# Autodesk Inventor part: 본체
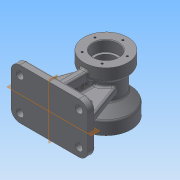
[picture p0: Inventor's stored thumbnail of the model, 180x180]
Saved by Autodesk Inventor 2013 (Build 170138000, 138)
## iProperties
Created: 2015-08
Part Number: 본체
Material: 일반
Document SubType Name: Modeling
Designer: WINDOWS7
Density: 1 g/cm^3
Author: WINDOWS7
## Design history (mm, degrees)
sketch "스케치1"
  geometry: 1 further point
sketch "스케치2"
  geometry: C1 r 26 at (0, 90); 1 further point
  constraints: 1 centre point, 1 vertical alignment
  dimensions: "d0" = 52 diameter of C1; "d2" = 90 distance of C1.centre point (0, 0)
extrude "돌출1" new body sketch "스케치2" distance "d3" = 90; taper "d4" = 0 deg
sketch "스케치3"
  geometry: C1 r 26 at (0, 0) reference; C2 r 35 at (0, 0); 1 further point
  constraints: 1 centre point, 1 coincident
  dimensions: "d5" = 70 diameter of C2
extrude "돌출2" join sketch "스케치3" distance "d7" = 20; taper "d8" = 0 deg
sketch "스케치4"
  geometry: C1 r 26 at (0, 0) reference; C2 r 40 at (0, 0); 1 further point
  constraints: 1 centre point, 1 coincident
  dimensions: "d9" = 80 diameter of C2
extrude "돌출3" join sketch "스케치4" distance "d11" = 20; taper "d12" = 0 deg
sketch "스케치5"
  geometry: L1 (125, 0)-(125, -20) reference; L2 (116, -20)-(116, -70) reference; L3 (130, -90)-(130, -70) reference; L4 (55, 0)-(55, -20) reference; L5 (64, -20)-(64, -70) reference; L6 (55, 0)-(125, 0) reference; L7 (64, -20)-(116, -20) reference; L8 (116, -70)-(64, -70) reference; L9 (130, -90)-(50, -90) reference; L10 (90, 0)-(90, -90); L11 (125, -20)-(116, -25.196); L12 (130, -70)-(116, -53.315); L13 (116, -25.196)-(116, -20); L14 (116, -53.315)-(116, -70); 1 further point
  constraints: 10 end point, 2 midpoint, 2 point on line, 1 collinear, 1 parallel
  dimensions: "d13" = 60 deg angle of L2 L11; "d14" = 40 deg angle of L2 L12
revolve "회전1" sketch "스케치5" stored, may be unused: angle "d15" = 90 deg
sketch "스케치6"
  geometry: L1 (61, 0.744)-(-61, 0.744); L2 (-61, 0.744)-(-61, -79.256); L3 (-61, -79.256)-(61, -79.256); L4 (61, -79.256)-(61, 0.744); L5 (26, -25.196)-(26, -53.315) reference; L6 (-26, -25.196)-(-26, -53.315) reference; L7 (-35, 0)-(35, 0) reference; 4 further points
  constraints: 8 end point, 3 midpoint, 2 parallel, 1 horizontal, 1 horizontal alignment, 1 perpendicular, 1 vertical alignment
  dimensions: "d16" = 80 distance of L3.end L1.start; "d18" = 122 distance of L2.end L3.end
extrude "돌출4" join sketch "스케치6" distance "d19" = 12; taper "d20" = 0 deg
node "작업 평면1"
sketch "스케치7"
  geometry: L1 (122, 0)-(0, 0) reference; L2 (0, 0)-(0, 12) reference; L3 (122, 12)-(0, 12) reference; L4 (122, 0)-(122, 12) reference; L5 (10, 12)-(37.488, 87.523); L6 (37.488, 87.523)-(84.512, 87.523); L7 (84.512, 87.523)-(112, 12); 1 further point
  constraints: 6 end point, 2 point on line, 1 perpendicular
  dimensions: "d22" = 10 distance of L3.start L7.end; "d23" = 70 deg angle of L3 L7; "d24" = 10 distance of L2.end L5.start; "d25" = 70 deg angle of L3 L5; "d26" = 47.02406 distance of L5.end L6.end
extrude "돌출5" join sketch "스케치7" stored distance "d27" = 12; taper "d28" = 0 deg
node "작업 평면2"
sketch "스케치8"
  geometry: L1 (80, 12)-(0, 12) reference; L2 (80, 0)-(0, 0) reference; L3 (0, 0)-(0, 12) reference; L4 (80, 12)-(0, 12) reference; L5 (80, 0)-(80, 12) reference; L6 (10, 83.257)-(10, 12); L7 (10, 83.257)-(82.565, 83.257); L8 (82.565, 83.257)-(70, 12); 1 further point
  constraints: 6 end point, 2 perpendicular, 2 point on line, 1 parallel
  dimensions: "d30" = 10 distance of L8.end L1.start; "d31" = 80 deg angle of L1 L8; "d32" = 10 distance of L1.end L6.end; "d33" = 72.5645 distance of L6.start L7.end
extrude "돌출6" join sketch "스케치8" stored distance "d34" = 12; taper "d35" = 0 deg
sketch "스케치9"
  geometry: L1 (79, 42)-(91, 42); L2 (91, 42)-(91, 24); L3 (91, 24)-(79, 24); L4 (79, 24)-(79, 42); A1 r 6 centre (85, 36) between (91, 36) and (79, 36); A2 r 6 centre (85, 30) between (79, 30) and (91, 30); 1 further point
  constraints: 8 end point, 5 point on circle, 4 point on line, 2 centre point, 2 parallel, 2 tangent, 1 equal radius, 1 horizontal, 1 perpendicular, 1 vertical alignment
  dimensions: "d36" = 12 distance of L1.start L1.end; "d38" = 18 distance of L3.end L1.start; "d39" = 12 diameter of A1; "d40" = 24 horizontal distance of point (61, 0) A2.centre; "d41" = 30 vertical distance of point (61, 0) A2.centre
extrude "돌출7" cut sketch "스케치9" distance "d42" = 12; taper "d43" = 0 deg
sketch "스케치10"
  geometry: C1 r 20 at (0, 90); A1 r 35 centre (0, 90) between (0, 125) and (35, 90) reference; 1 further point
  constraints: 1 centre point, 1 coincident
  dimensions: "d44" = 40 diameter of C1
extrude "돌출8" cut sketch "스케치10" distance "d46" = 17; taper "d47" = 0 deg
sketch "스케치11"
  geometry: C1 r 26 at (0, 90); A1 r 40 centre (0, 90) between (0, 130) and (40, 90) reference; 1 further point
  constraints: 1 centre point, 1 coincident
  dimensions: "d48" = 52 diameter of C1
extrude "돌출9" cut sketch "스케치11" distance "d50" = 20; taper "d51" = 0 deg
sketch "스케치12"
  geometry: L1 (6, -39.547)-(6, -25.298) reference; L2 (-6, -25.298)-(-6, -39.547) reference; C1 r 19 at (0, 0); A1 r 26 centre (0, 0) between (6, -25.298) and (-6, -25.298) reference; A2 r 40 centre (0, 0) between (6, -39.547) and (-6, -39.547) reference; 1 further point
  constraints: 1 centre point, 1 coincident
  dimensions: "d52" = 38 diameter of C1
extrude "돌출10" cut sketch "스케치12" distance "d54" = 3; taper "d55" = 0 deg
sketch "스케치13"
  geometry: C1 r 16 at (0, 0); A1 r 35 centre (0, 0) between (6, -34.482) and (-6, -34.482) reference; 1 further point
  constraints: 1 centre point, 1 coincident
  dimensions: "d56" = 32 diameter of C1
extrude "돌출11" cut sketch "스케치13" stored distance "d58" = 3; taper "d59" = 0 deg
sketch "스케치14"
  geometry: A1 r 40 centre (0, 90) between (0, 130) and (40, 90) reference; 3 further points
  constraints: 2 vertical alignment, 1 coincident, 2 other
  dimensions: "d60" = 33 distance of A1.centre point (0, 123)
hole "구멍1" sketch "스케치14" at (0, 123) diameter "d61" = 3.242; stored, may be unused: countersink angle "d65" = 90 deg, drill point angle "d67" = 118 deg; dims "d62" = 10, "d63" = 4, "d64" = 2, "d66" = 13
sketch "스케치15" dims "d71" = 54
  geometry: A1 r 35 centre (0, 90) between (0, 125) and (35, 90) reference; 3 further points
  constraints: 2 vertical alignment, 1 coincident, 2 other
hole "구멍2" sketch "스케치15" at (0, 117) diameter "d73" = 3.242; stored, may be unused: countersink angle "d77" = 90 deg, drill point angle "d79" = 118 deg; dims "d74" = 10, "d75" = 4, "d76" = 2, "d78" = 13
sketch "스케치16"
  geometry: L1 (-61, -0.744)-(61, -0.744) reference; L2 (-61, 79.256)-(-61, -0.744) reference; L3 (61, 79.256)-(-61, 79.256) reference; L4 (61, -0.744)-(61, 79.256) reference; C1 r 6 at (-47, 65.256); C2 r 6 at (-47, 13.256); C3 r 6 at (47, 13.256); C4 r 6 at (47, 65.256); 1 further point
  constraints: 4 centre point, 3 equal radius, 2 horizontal alignment, 2 vertical alignment
  dimensions: "d83" = 12 diameter of C1; "d85" = 94 distance of C4.centre C1.centre; "d86" = 14 distance from line of L2 C1.centre; "d87" = 14 distance from line of L3 C1.centre; "d88" = 52 distance of C2.centre C1.centre
extrude "돌출12" cut sketch "스케치16" distance "d89" = 12; taper "d90" = 0 deg
sketch "스케치17"
  geometry: L1 (0, 0)-(80, 0) reference; L2 (80, 0)-(80, 12) reference; L3 (0, 12)-(80, 12) reference; L4 (0, 0)-(0, 12) reference; L5 (34, 64.702)-(34, 12) reference; L6 (25.94, 64.702)-(34, 64.702) reference; L7 (10, 55.518)-(20.744, 55.518) reference; L8 (10, 55.518)-(10, 12) reference; L9 (34, 12)-(10, 12) reference; 2 further points
  constraints: 2 other
  dimensions: "d91" = 16 distance from line of point (26, 36) L8; "d92" = 24 distance from line of point (26, 36) L3
feature "엠보싱1" sketch "스케치17" dims "d93" = 0.5, "d94" = 0
fillet "모깎기1" dims "d95" = 14
fillet "모깎기2" dims "d96" = 3
fillet "모깎기3" dims "d97" = 3
fillet "모깎기4" dims "d98" = 3
fillet "모깎기5" dims "d99" = 5
chamfer "모따기1" distance "d100" = 1; stored, may be unused: second distance "d101" = 2, angle "d102" = 45 deg
fillet "모깎기6" dims "d103" = 0.3
fillet "모깎기7" dims "d104" = 0.3
fillet "모깎기8" dims "d105" = 3
fillet "모깎기9" dims "d106" = 3
node "솔리드1"
mirror "대칭1"
pattern_circular "원형 패턴1" dims angle "d69" = 360 deg
pattern_circular "원형 패턴2" dims angle "d81" = 360 deg
node "투영된 루프1"
node "투영된 루프2"
node "투영된 루프3"
node "투영된 루프4"
node "투영된 루프5"
node "투영된 루프6"
other parameters: "d29" = -61
